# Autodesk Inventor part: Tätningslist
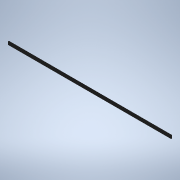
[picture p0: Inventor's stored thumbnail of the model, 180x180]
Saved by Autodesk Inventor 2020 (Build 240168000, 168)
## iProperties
Created: 2019-06
Part Number: Tätningslist
Material: Acetal Resin, Black
Document SubType Name: Modeling
Designer: cl
Density: 1.425 g/cm^3
Appearance: Smooth - Black
Author: cl
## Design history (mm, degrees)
sketch "Sketch1"
  geometry: L1 (4.9, 0)-(60, 0); L2 (60, 0)-(60, -14.8); L3 (60, -14.8)-(4.9, -14.8); L4 (0, -9.9)-(0, -4.9); A1 r 4.9 centre (4.9, -9.9) between (0, -9.9) and (4.9, -14.8); A2 r 4.9 centre (4.9, -4.9) between (4.9, 0) and (0, -4.9); 2 further points
  constraints: 8 end point, 4 point on circle, 4 point on line, 4 tangent, 2 centre point, 2 parallel, 1 equal radius, 1 horizontal, 1 perpendicular
  dimensions: "d0" = 60 distance of L2.end point (0, -14.8); "d1" = 14.8 distance of L1.end L2.end; "d2" = 4.9 radius of A1
extrude "Extrusion1" new body sketch "Sketch1" distance "d3" = 2970 (computed from Dagbredd); taper "d4" = 0 deg
body "Solid1"
